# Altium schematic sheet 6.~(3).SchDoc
size 420 x 297 mm
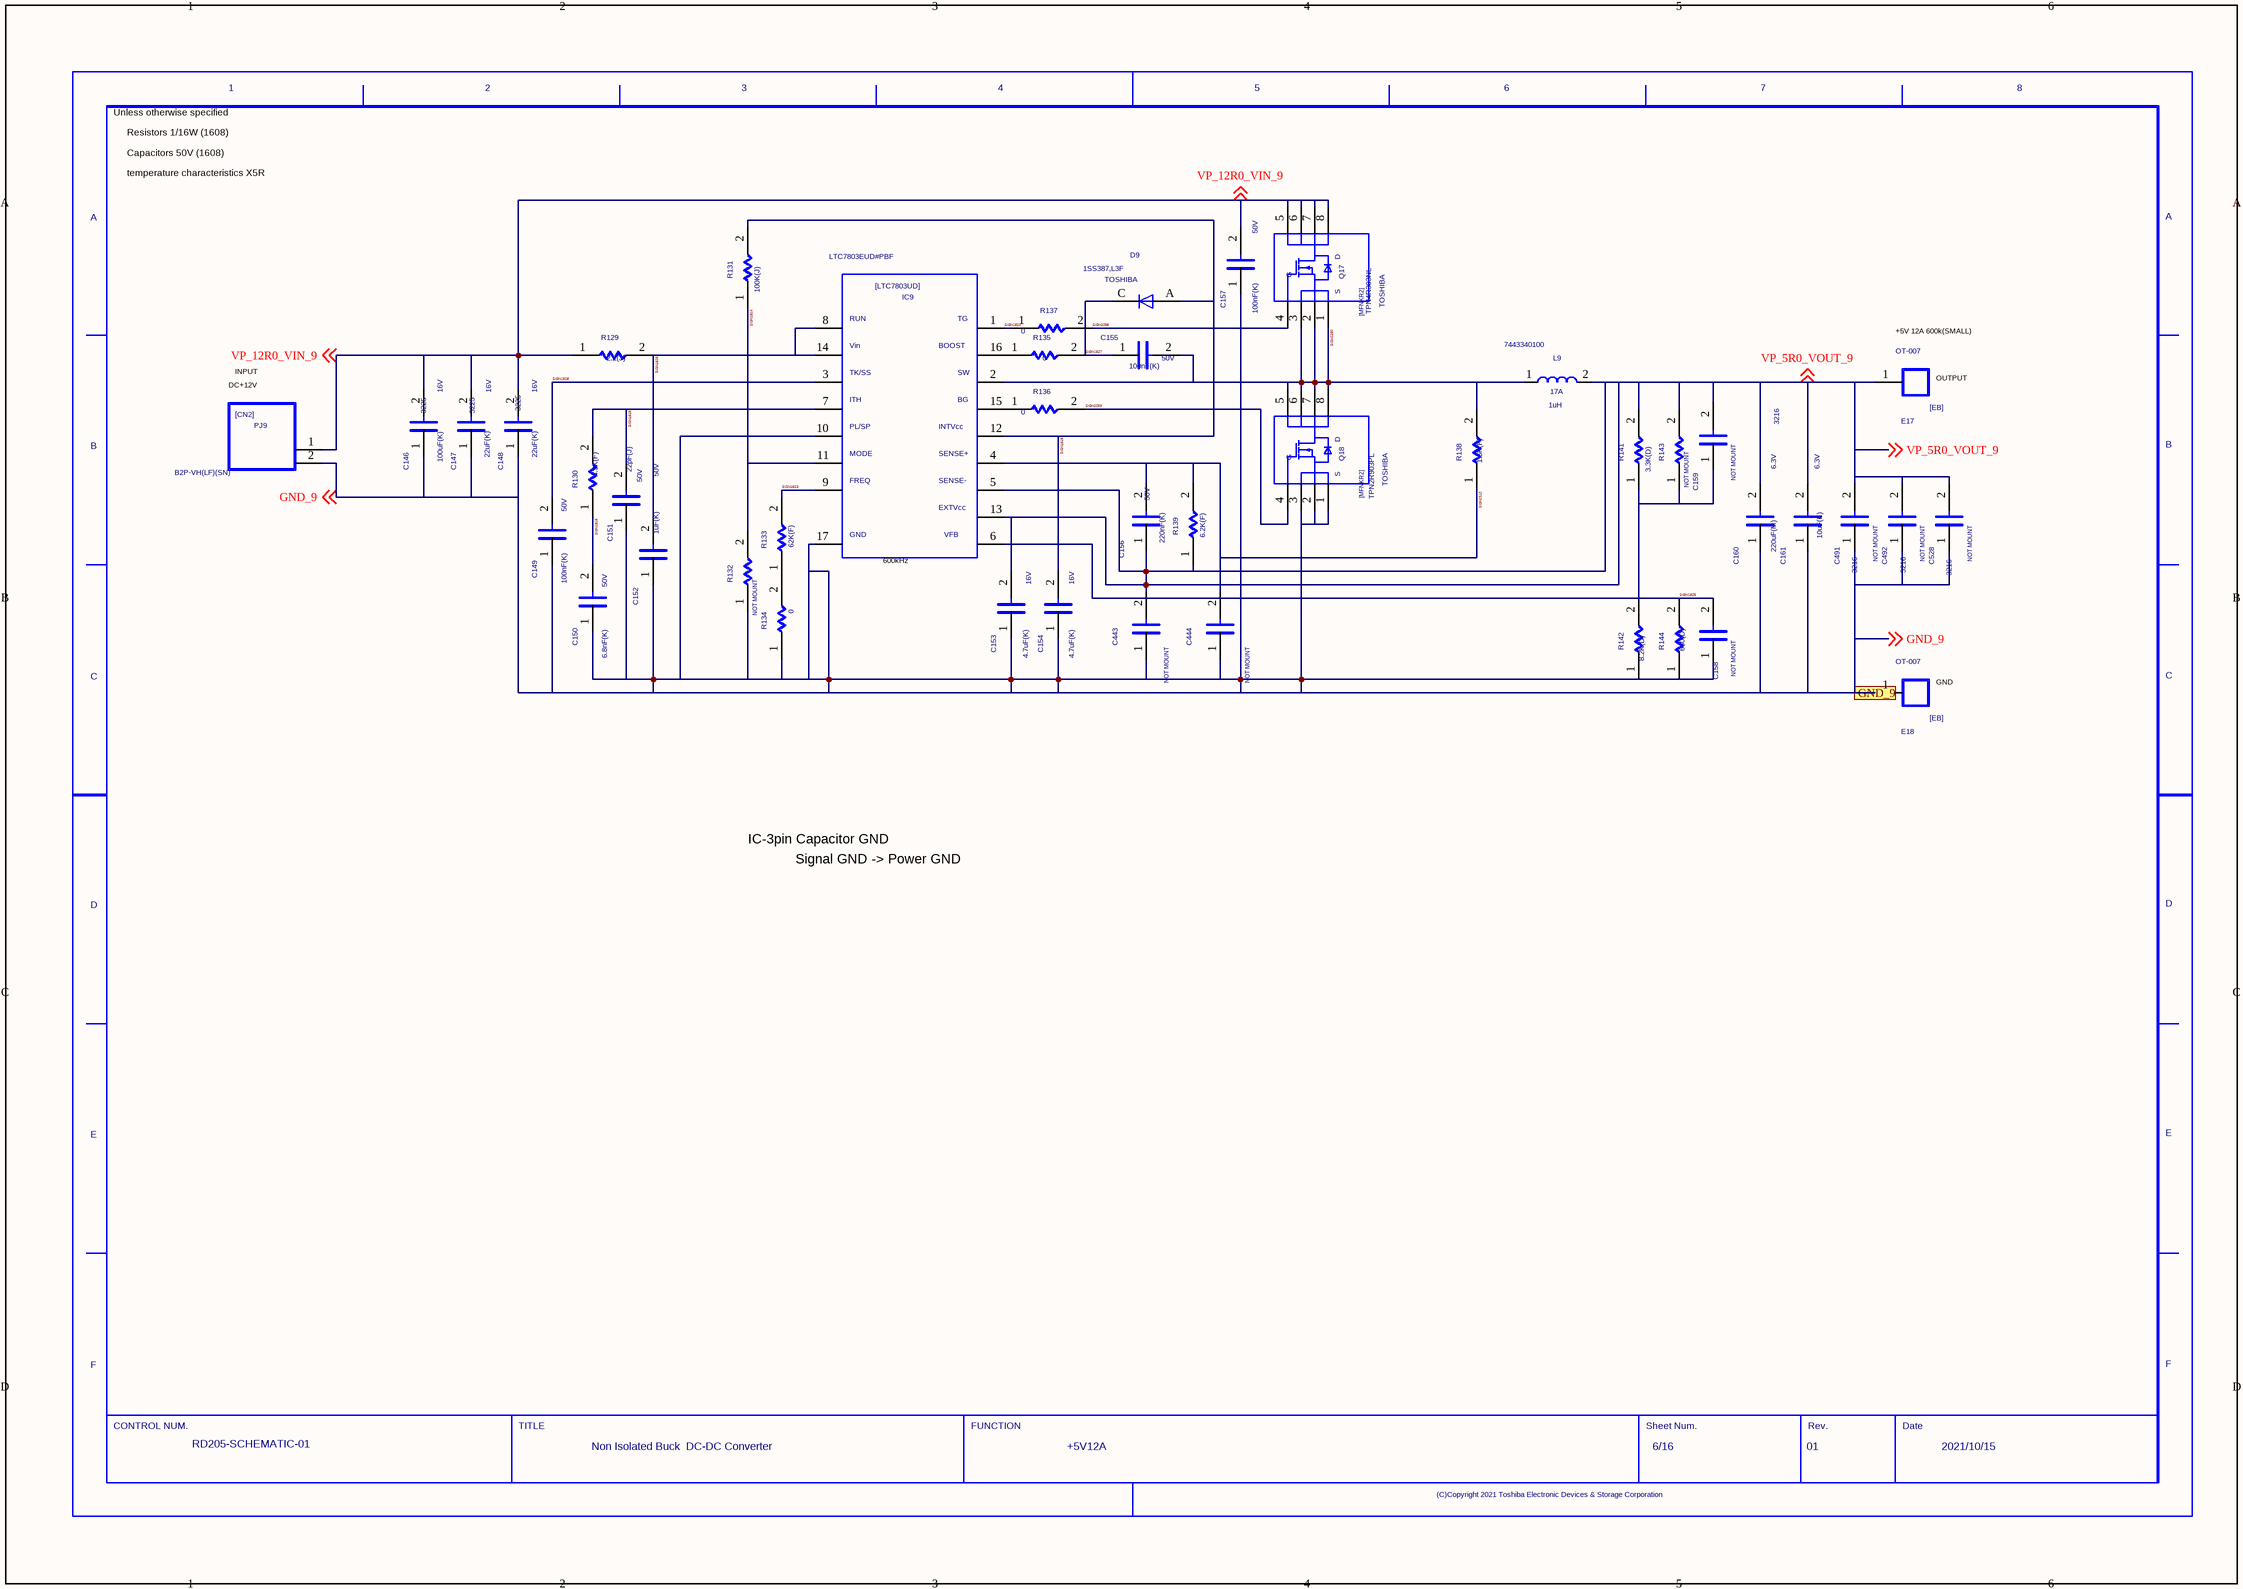
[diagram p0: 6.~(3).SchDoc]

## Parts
C146  SIZECODESMD: 3225  VAL2: 16V  VAL1: 100uF(K)  (hidden comment: C)
C147  SIZECODESMD: 3225  VAL2: 16V  VAL1: 22uF(K)  (hidden comment: C)
C148  SIZECODESMD: 3225  VAL2: 16V  VAL1: 22uF(K)  (hidden comment: C)
C149  VAL2: 50V  VAL1: 100nF(K)  (hidden comment: C)
C150  VAL2: 50V  VAL1: 6.8nF(K)  (hidden comment: C)
C151  VAL2: 50V  VAL1: 22pF(J)  (hidden comment: C)
C152  VAL2: 50V  VAL1: 1uF(K)  (hidden comment: C)
C153  VAL2: 16V  VAL1: 4.7uF(K)  (hidden comment: C)
C154  VAL2: 16V  VAL1: 4.7uF(K)  (hidden comment: C)
C155  VAL2: 50V  VAL1: 100nF(K)  (hidden comment: C)
C156  VAL2: 50V  VAL1: 220nF(K)  (hidden comment: C)
C157  VAL2: 50V  VAL1: 100nF(K)  (hidden comment: C)
C158  NOTMOUNT: NOT MOUNT  (hidden comment: C)
C159  NOTMOUNT: NOT MOUNT  (hidden comment: C)
C160  SIZECODESMD: 3216  VAL2: 6.3V  VAL1: 220uF(M)  (hidden comment: C)
C161  VAL2: 6.3V  VAL1: 10uF(K)  (hidden comment: C)
C443  NOTMOUNT: NOT MOUNT  (hidden comment: C)
C444  NOTMOUNT: NOT MOUNT  (hidden comment: C)
C491  NOTMOUNT: NOT MOUNT  SIZECODESMD: 3216  (hidden comment: C)
C492  NOTMOUNT: NOT MOUNT  SIZECODESMD: 3216  (hidden comment: C)
C528  NOTMOUNT: NOT MOUNT  SIZECODESMD: 3216  (hidden comment: C)
D9  USERCOMPTEXT3: TOSHIBA  VAL3: 1SS387,L3F  (hidden comment: D)
E17  VAL3: OT-007  (hidden comment: EB)
E18  VAL3: OT-007  (hidden comment: EB)
IC9  VAL3: LTC7803EUD#PBF  (hidden comment: LTC7803UD)
L9  VAL3: 7443340100  VAL2: 17A  VAL1: 1uH  (hidden comment: L)
PJ9  VAL3: B2P-VH(LF)(SN)  (hidden comment: CN2)
Q17  USERCOMPTEXT3: TOSHIBA  VAL3: TPN4R303NL  (hidden comment: MFNKR2)
Q18  USERCOMPTEXT3: TOSHIBA  VAL3: TPN2R903PL  (hidden comment: MFNKR2)
R129  VAL1: 2.2(J)  (hidden comment: R)
R130  VAL1: 4.3K(F)  (hidden comment: R)
R131  VAL1: 100K(J)  (hidden comment: R)
R132  NOTMOUNT: NOT MOUNT  (hidden comment: R)
R133  VAL1: 62K(F)  (hidden comment: R)
R134  VAL1: 0  (hidden comment: R)
R135  VAL1: 0  (hidden comment: R)
R136  VAL1: 0  (hidden comment: R)
R137  VAL1: 0  (hidden comment: R)
R138  VAL1: 1.5K(F)  (hidden comment: R)
R139  VAL1: 6.2K(F)  (hidden comment: R)
R141  VAL1: 3.3K(D)  (hidden comment: R)
R142  VAL1: 8.2K(D)  (hidden comment: R)
R143  NOTMOUNT: NOT MOUNT  (hidden comment: R)
R144  VAL1: 680(D)  (hidden comment: R)
U?  DATE: 2021/10/15  SHEETNUMBER: 6/16  TITLE: Non Isolated Buck / DC-DC Converter  REVISION: 01  DRAWINGNUMBER: RD205-SCHEMATIC-01  FUNCTION: +5V12A  (hidden comment: WAKU_DEF100)

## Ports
GND_9

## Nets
GND_9: C146.1 C147.1 C148.1 C149.1 C150.1 C151.1 C152.1 C153.1 C154.1 C157.1 C158.1 C160.1 C161.1 C443.1 C444.1 C491.1 C492.1 C528.1 E18.1 IC9.10 IC9.17 PJ9.2 Q18.1 Q18.2 Q18.3 R132.1 R134.1 R142.1 R144.1 ; off-sheet GND_9, port GND_9
SIGN1814: IC9.11 R131.1 R132.2
SIGN1815: C154.2 D9.A IC9.12 R131.2
SIGN1816: C150.2 R130.1
SIGN1819: C151.2 IC9.7 R130.2
SIGN1822: IC9.1 R137.1
SIGN1823: IC9.9 R133.2
SIGN1825: C158.2 C159.1 IC9.6 R141.1 R142.2 R143.1 R144.2
SIGN1826: C152.2 IC9.8 IC9.14 R129.2
SIGN1827: C155.1 D9.C R135.2
SIGN1828: C149.2 IC9.3
SIGN2258: Q17.4 R137.2
SIGN2259: Q18.4 R136.2
SIGN2260: C155.2 IC9.2 L9.1 Q17.1 Q17.2 Q17.3 Q18.5 Q18.6 Q18.7 Q18.8 R138.2
SIGN2312: C156.2 C444.2 IC9.4 R138.1 R139.2
VP_5R0_VOUT_9: C153.2 C156.1 C159.2 C160.2 C161.2 C443.2 C491.2 C492.2 C528.2 E17.1 IC9.5 IC9.13 L9.2 R139.1 R141.2 R143.2 ; off-sheet VP_5R0_VOUT_9
VP_12R0_VIN_9: C146.2 C147.2 C148.2 C157.2 PJ9.1 Q17.5 Q17.6 Q17.7 Q17.8 R129.1 ; off-sheet VP_12R0_VIN_9
NetIC9_15: IC9.15 R136.1
NetIC9_16: IC9.16 R135.1
NetR133_1: R133.1 R134.2

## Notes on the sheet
- Unless otherwise specified
- Resistors 1/16W (1608)
- Capacitors 50V (1608)
- temperature characteristics X5R
- DC+12V
- INPUT
- (near E17) +5V 12A 600k(SMALL)
- (near E17) OUTPUT
- (near IC9) 600kHz
- (near E18) GND
- IC-3pin Capacitor GND
- Signal GND -> Power GND

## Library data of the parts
C146 = C: SQ_PART_MODEL: CON_100n; FNPARTSNAMEG: CHIP CERAMIC CAPACITOR (3225); USEINPARTSLIST: YES; OriginalSymbolOrigin: (2540,7620); MFSOLDERINGPROP: .; TEMPCHARACTERI2: B; MFFORMINGDIVP: KC; OUMECLASSIFICATION: セラミックコンデンサ; MFMOUNTSYMBOLP: 90; CDMASTERCADCELG: DC903A; PCODE: P03276001115; FNCLASSCODEG: P03-03; MAXGCOUNT: 1; RATEDVOLTAGE: 250; COMPONENTNAME: G36030160049; OUMEMAKER: KYC 京セラ; MFPACKAGEMETHOP: S; NOMINALCAPACITA: 100n; OUMEMAKERKATAMEI: CF32W5R104K250AT; CAPACITANCETOLE: K
C147 C148 = C: SQ_PART_MODEL: CON_22u; FNPARTSNAMEG: CHIP CERAMIC CAPACITOR (3225); USEINPARTSLIST: YES; OriginalSymbolOrigin: (2540,7620); MFSOLDERINGPROP: .; TEMPCHARACTERI2: B; MFFORMINGDIVP: KC; OUMECLASSIFICATION: セラミックコンデンサ; MFMOUNTSYMBOLP: 80; CDMASTERCADCELG: DC903A; PCODE: P03043035626; FNCLASSCODEG: P03-03; MAXGCOUNT: 1; RATEDVOLTAGE: 6.3; COMPONENTNAME: G36030119054; OUMEMAKER: TYD 太陽誘電; MFPACKAGEMETHOP: S; NOMINALCAPACITA: 22u; OUMEMAKERKATAMEI: JMK325BJ226KM-T; CAPACITANCETOLE: K
C149 C155 C157 = C: SQ_PART_MODEL: CON_100n; FNPARTSNAMEG: CHIP CERAMIC CAPACITOR (1608); USEINPARTSLIST: YES; OriginalSymbolOrigin: (2540,7620); MFSOLDERINGPROP: .; TEMPCHARACTERI2: B; MFFORMINGDIVP: KC; OUMECLASSIFICATION: セラミックコンデンサ; SIZECODESMD: 1608; MFMOUNTSYMBOLP: 80; CDMASTERCADCELG: C8100E; PCODE: P03B000000E4; FNCLASSCODEG: P03-03; MAXGCOUNT: 1; RATEDVOLTAGE: 16; COMPONENTNAME: GDM030000598; OUMEMAKER: MRT 村田製作所; MFPACKAGEMETHOP: S; NOMINALCAPACITA: 100n; OUMEMAKERKATAMEI: GRM188B11C104KA01C; CAPACITANCETOLE: K
C150 = C: SQ_PART_MODEL: CON_6.8n; FNPARTSNAMEG: CHIP CERAMIC CAPACITOR (1608); USEINPARTSLIST: YES; OriginalSymbolOrigin: (2540,7620); TOLERANCE: K; ASIMVALUE: 6.8N; MFSOLDERINGPROP: .; TEMPCHARACTERI2: B; MFFORMINGDIVP: KC; OUMECLASSIFICATION: セラミックコンデンサ; SIZECODESMD: 1608; MFMOUNTSYMBOLP: 80; CDMASTERCADCELG: C8100E; PCODE: P03039109225; FNCLASSCODEG: P03-03; MAXGCOUNT: 1; RATEDVOLTAGE: 50; COMPONENTNAME: G36030011440; OUMEMAKER: MRT 村田製作所; MFPACKAGEMETHOP: S; OUMEMAKERKATAMEI: GRM39B682K50PT
C151 = C: SQ_PART_MODEL: CON_22p; FNPARTSNAMEG: CHIP CERAMIC CAPACITOR (1608); USEINPARTSLIST: YES; OriginalSymbolOrigin: (2540,7620); TOLERANCE: J; ASIMVALUE: 22P; MFSOLDERINGPROP: .; TEMPCHARACTERI2: CH; MFFORMINGDIVP: KC; OUMECLASSIFICATION: セラミックコンデンサ; SIZECODESMD: 1608; MFMOUNTSYMBOLP: 80; CDMASTERCADCELG: C8100E; PCODE: P03039A02625; FNCLASSCODEG: P03-03; MAXGCOUNT: 1; RATEDVOLTAGE: 50; COMPONENTNAME: G36030011129; OUMEMAKER: TYD 太陽誘電; MFPACKAGEMETHOP: S; OUMEMAKERKATAMEI: UMK107CH220JZ-T
C152 = C: SQ_PART_MODEL: CON_1u; FNPARTSNAMEG: CHIP CERAMIC CAPACITOR (1608); USEINPARTSLIST: YES; OriginalSymbolOrigin: (2540,7620); MFSOLDERINGPROP: .; TEMPCHARACTERI2: B; MFFORMINGDIVP: KC; OUMECLASSIFICATION: セラミックコンデンサ; SIZECODESMD: 1608; MFMOUNTSYMBOLP: 80; CDMASTERCADCELG: C8100E; PCODE: P03039ACE122; FNCLASSCODEG: P03-03; MAXGCOUNT: 1; RATEDVOLTAGE: 6.3; COMPONENTNAME: G36030104159; OUMEMAKER: KYC 京セラ; MFPACKAGEMETHOP: S; NOMINALCAPACITA: 1u; OUMEMAKERKATAMEI: CM105B105K06ATN; CAPACITANCETOLE: K
C153 = C: SQ_PART_MODEL: CON_4.7u; FNPARTSNAMEG: CHIP CERAMIC CAPACITOR (1608); USEINPARTSLIST: YES; OriginalSymbolOrigin: (2540,7620); PCODE: P03B000000MS; MFSOLDERINGPROP: .; TEMPCHARACTERI2: B; MFFORMINGDIVP: KC; OUMECLASSIFICATION: セラミックコンデンサ; SIZECODESMD: 1608; MFMOUNTSYMBOLP: 80; CDMASTERCADCELG: C8100E; FNCLASSCODEG: P03-03; MAXGCOUNT: 1; RATEDVOLTAGE: 4; COMPONENTNAME: GDM030000053; OUMEMAKER: KYC 京セラ; MFPACKAGEMETHOP: S; NOMINALCAPACITA: 4.7u; OUMEMAKERKATAMEI: CM105B475M04AT; CAPACITANCETOLE: M
C154 = C: SQ_PART_MODEL: CON_4.7u; FNPARTSNAMEG: CHIP CERAMIC CAPACITOR (1608); USEINPARTSLIST: YES; OriginalSymbolOrigin: (2540,7620); MFSOLDERINGPROP: .; TEMPCHARACTERI2: B; MFFORMINGDIVP: KC; OUMECLASSIFICATION: セラミックコンデンサ; SIZECODESMD: 1608; MFMOUNTSYMBOLP: 80; CDMASTERCADCELG: C8100E; PCODE: P03B000000MS; FNCLASSCODEG: P03-03; MAXGCOUNT: 1; RATEDVOLTAGE: 4; COMPONENTNAME: GDM030000053; OUMEMAKER: KYC 京セラ; MFPACKAGEMETHOP: S; NOMINALCAPACITA: 4.7u; OUMEMAKERKATAMEI: CM105B475M04AT; CAPACITANCETOLE: M
C156 = C: SQ_PART_MODEL: CON_220n; FNPARTSNAMEG: CHIP CERAMIC CAPACITOR (1608); PARTCOMMENT: 代表セル<KC0008> がフットプリントに登録されていません。; USEINPARTSLIST: YES; OriginalSymbolOrigin: (2540,7620); MFSOLDERINGPROP: .; TEMPCHARACTERI2: B; MFFORMINGDIVP: KC; OUMECLASSIFICATION: セラミックコンデンサ; SIZECODESMD: 1608; MFMOUNTSYMBOLP: 80; CDMASTERCADCELG: KC0008; PCODE: P03B000001L3; FNCLASSCODEG: P03-03; MAXGCOUNT: 1; RATEDVOLTAGE: 16; COMPONENTNAME: GDM030001129; OUMEMAKER: MRT 村田製作所; MFPACKAGEMETHOP: S; NOMINALCAPACITA: 220n; OUMEMAKERKATAMEI: GRM188B11C224KA01D; CAPACITANCETOLE: K
C158 C159 = C: SQ_PART_MODEL: CON_100p; FNPARTSNAMEG: CHIP CERAMIC CAPACITOR (1608); USEINPARTSLIST: YES; OriginalSymbolOrigin: (2540,7620); TOLERANCE: J; ASIMVALUE: 100P; MFSOLDERINGPROP: .; TEMPCHARACTERI2: CH; MFFORMINGDIVP: KC; OUMECLASSIFICATION: セラミックコンデンサ; SIZECODESMD: 1608; MFMOUNTSYMBOLP: 80; CDMASTERCADCELG: C8100E; PCODE: P03039177125; FNCLASSCODEG: P03-03; MAXGCOUNT: 1; RATEDVOLTAGE: 50; COMPONENTNAME: G36030011365; OUMEMAKER: KYC 京セラ; MFPACKAGEMETHOP: S; OUMEMAKERKATAMEI: CM105CH101J50AT; VAL2: 50V; VAL1: 100pF(J)
C160 = C: SQ_PART_MODEL: CON_22u; FNPARTSNAMEG: CHIP CERAMIC CAPACITOR (3216); USEINPARTSLIST: YES; OriginalSymbolOrigin: (2540,7620); MFSOLDERINGPROP: .; TEMPCHARACTERI2: B; MFFORMINGDIVP: KC; OUMECLASSIFICATION: セラミックコンデンサ; MFMOUNTSYMBOLP: 80; CDMASTERCADCELG: DC901A; PCODE: P03B0000004V; FNCLASSCODEG: P03-03; MAXGCOUNT: 1; RATEDVOLTAGE: 6.3; COMPONENTNAME: GDM030000020; OUMEMAKER: KYC 京セラ; MFPACKAGEMETHOP: S; NOMINALCAPACITA: 22u; OUMEMAKERKATAMEI: CM316B226M06AT; CAPACITANCETOLE: M
C161 = C: SQ_PART_MODEL: CON_1u; FNPARTSNAMEG: CHIP CERAMIC CAPACITOR (1608); PARTCOMMENT: 代表セル<KC0008> がフットプリントに登録されていません。; USEINPARTSLIST: YES; OriginalSymbolOrigin: (2540,7620); MFSOLDERINGPROP: .; TEMPCHARACTERI2: B; MFPACKAGEMETHOP: S; MFFORMINGDIVP: KC; MFMOUNTSYMBOLP: 80; PCODE: P03B000000ZQ; OUMECLASSIFICATION: セラミックコンデンサ; SIZECODESMD: 1608; CDMASTERCADCELG: KC0008; FNCLASSCODEG: P03-03; MAXGCOUNT: 1; RATEDVOLTAGE: 6.3; COMPONENTNAME: GDM030000202; OUMEMAKER: MRT 村田製作所; NOMINALCAPACITA: 1u; OUMEMAKERKATAMEI: GRM185B10J105KE21D; CAPACITANCETOLE: K
C443 C444 = C: SQ_PART_MODEL: CON_220n; FNPARTSNAMEG: CHIP CERAMIC CAPACITOR (1608); PARTCOMMENT: 代表セル<KC0008> がフットプリントに登録されていません。; USEINPARTSLIST: YES; OriginalSymbolOrigin: (2540,7620); MFSOLDERINGPROP: .; TEMPCHARACTERI2: B; MFFORMINGDIVP: KC; OUMECLASSIFICATION: セラミックコンデンサ; SIZECODESMD: 1608; MFMOUNTSYMBOLP: 80; CDMASTERCADCELG: KC0008; PCODE: P03B000001L3; FNCLASSCODEG: P03-03; MAXGCOUNT: 1; RATEDVOLTAGE: 16; COMPONENTNAME: GDM030001129; OUMEMAKER: MRT 村田製作所; MFPACKAGEMETHOP: S; NOMINALCAPACITA: 220n; OUMEMAKERKATAMEI: GRM188B11C224KA01D; VAL2: 16V; VAL1: 220nF(K); CAPACITANCETOLE: K
C491 C492 C528 = C: SQ_PART_MODEL: CON_22u; FNPARTSNAMEG: CHIP CERAMIC CAPACITOR (3216); USEINPARTSLIST: YES; OriginalSymbolOrigin: (2540,7620); MFSOLDERINGPROP: .; TEMPCHARACTERI2: B; MFFORMINGDIVP: KC; OUMECLASSIFICATION: セラミックコンデンサ; MFMOUNTSYMBOLP: 80; CDMASTERCADCELG: DC901A; PCODE: P03B0000004V; FNCLASSCODEG: P03-03; MAXGCOUNT: 1; RATEDVOLTAGE: 6.3; COMPONENTNAME: GDM030000020; OUMEMAKER: KYC 京セラ; MFPACKAGEMETHOP: S; NOMINALCAPACITA: 22u; OUMEMAKERKATAMEI: CM316B226M06AT; VAL2: 6.3V; VAL1: 22uF(M); CAPACITANCETOLE: M
D9 = D: FNPARTSNAMEG: DIODE; USEINPARTSLIST: YES; PARTNAME: GDM420000143; SAVEAREA0: -565,-171,12979,8058; SAVECOUNT: 1; TIME: 14:49:55; UPDATEUSER: 19870035; UPDATETIME: 14:20:16; OriginalSymbolOrigin: (5080,5080); FORWARDVOLTAGEM: 0; MAXREVERSEVOLTA: 80; COMPONENTNAME: GDM420000143_package; MFSOLDERINGPROP: .; OUMEMAKER: TSB 東芝（ＹＰＳＳ）; QUADMODEL: dummymodel; MFPACKAGEMETHOP: S; MFFORMINGDIVP: MM; MOUNTINGFORMSMD: SMD; OUMECLASSIFICATION: 小信号ダイオード; OUMEMAKERKATAMEI: 1SS387(TPH3,F); CDMASTERCADCELG: D8101D; PCODE: P42B0000008E; FNCLASSCODEG: P42-01
E17 E18 = EB: FNPARTSNAMEG: TERMINAL; USEINPARTSLIST: YES; PARTNAME: 5P9L1232P001; OUMEPARTTYPE: TB; OriginalSymbolOrigin: (2540,12700); COMPONENTNAME: 5P9L1232P001_package; MAXGCOUNT: 1; MFSOLDERINGPROP: .; OUMEMAKER: オサダ; QUADMODEL: dummymodel; MFPACKAGEMETHOP: I; MFFORMINGDIVP: OD; OUMECLASSIFICATION: 端子台、端子板; CDMASTERCADCELG: DE0009; KIND: PBS; PCODE: P29045001117; TERMINALSTYLE: SC; FNCLASSCODEG: P29-01
IC9 = LTC7803UD: USEINPARTSLIST: YES; SAVECOUNT: 29; SAVEAREA0: -53177,0,89020,58420; TIME: 16:14:14; UPDATEUSER: q91866sr; UPDATETIME: 13:15:36; OriginalSymbolOrigin: (5080,55880); MAXGCOUNT: 1; COMPONENTNAME: LTC7803UD_LTC7803UD; OUMEMAKER: ANALOG DEVICES
L9 = L: USEINPARTSLIST: YES; PARTNAME: 7443340068; OriginalSymbolOrigin: (2540,5080); MAXGCOUNT: 1; COMPONENTNAME: L_L; OUMEMAKER: WURTH
PJ9 = CN2: FNPARTSNAMEG: 3.96PITCH NYLON CONNECTOR; USEINPARTSLIST: YES; PARTNAME: G36220114012; OUMEPARTTYPE: CN; OriginalSymbolOrigin: (2540,15240); MAXGCOUNT: 1; RATEDCURRENT: 7; COMPONENTNAME: G36220114012_package; MFSOLDERINGPROP: .; OUMEMAKER: JST 日本圧着端子製造; NUMBEROFCONTACT: 2; QUADMODEL: dummymodel; MFPACKAGEMETHOP: I; MFFORMINGDIVP: CU; CONTACTPITCH: 3.96m; OUMEMAKERKATAMEI: B2P-VH; CDMASTERCADCELG: DPJ514; PCODE: P22346001114; TERMINALSTYLE: PW; FNCLASSCODEG: P22-10
Q17 Q18 = MFNKR2: USEINPARTSLIST: YES; PARTNAME: TPN1R603PL; SAVEAREA0: -9199,-39,32138,22820; TIME: 18:57:44; UPDATEUSER: q91866sr; UPDATETIME: 12:36:02; SAVECOUNT: 10; OriginalSymbolOrigin: (5080,20320); MAXGCOUNT: 1; COMPONENTNAME: MFNKR2_MFNKR2
R129 = R: SQ_PART_MODEL: RES_2.2; FNPARTSNAMEG: CHIP RESISTOR (1608); USEINPARTSLIST: YES; OriginalSymbolOrigin: (5080,5080); TOLERANCE: J; ASIMVALUE: 2.2; MAXGCOUNT: 1; COMPONENTNAME: G36010011507; MFSOLDERINGPROP: .; OUMEMAKER: NAE 松下電子部品; MFPACKAGEMETHOP: S; MFFORMINGDIVP: KC; MOUNTINGFORMSMD: SMD; OUMECLASSIFICATION: 表面実装用固定抵抗器; MFMOUNTSYMBOLP: 80; POWERRATING: 63m; OUMEMAKERKATAMEI: ERJ3GEYJ2R2V; NUMBEROFELEMENT: 0; VAL2: 62.5mW; CDMASTERCADCELG: DR802R; PCODE: P01042157622; FNCLASSCODEG: P01-08
R130 = R: SQ_PART_MODEL: RES_4.3K; FNPARTSNAMEG: CHIP RESISTOR (1608); USEINPARTSLIST: YES; OriginalSymbolOrigin: (5080,5080); PCODE: P01042335624; MAXGCOUNT: 1; COMPONENTNAME: G5101105L102; MFSOLDERINGPROP: .; OUMEMAKER: NAE 松下電子部品; MFPACKAGEMETHOP: S; MFFORMINGDIVP: KC; MOUNTINGFORMSMD: SMD; OUMECLASSIFICATION: 表面実装用固定抵抗器; RESISTANCETOLER: F; MFMOUNTSYMBOLP: 80; POWERRATING: 63m; OUMEMAKERKATAMEI: ERJ3GEYF432V; NOMINALRESISTAN: 4.3K; NUMBEROFELEMENT: 0; VAL2: 62.5mW; CDMASTERCADCELG: DR802R; FNCLASSCODEG: P01-08
R131 = R: SQ_PART_MODEL: RES_100K; FNPARTSNAMEG: CHIP RESISTOR (1608); USEINPARTSLIST: YES; OriginalSymbolOrigin: (5080,5080); TOLERANCE: J; ASIMVALUE: 100K; MFSOLDERINGPROP: .; MFPACKAGEMETHOP: S; MFFORMINGDIVP: KC; MOUNTINGFORMSMD: SMD; MFMOUNTSYMBOLP: 80; NUMBEROFELEMENT: 0; PCODE: P01042047220; MAXGCOUNT: 1; COMPONENTNAME: G36010011057; OUMEMAKER: HDK 北陸電気工業; OUMECLASSIFICATION: 表面実装用固定抵抗器; POWERRATING: 63m; OUMEMAKERKATAMEI: CR1/16 104JV; VAL2: 62.5mW; CDMASTERCADCELG: DR802R; FNCLASSCODEG: P01-08
R132 = R: SQ_PART_MODEL: RES_10; FNPARTSNAMEG: CHIP RESISTOR (1608); USEINPARTSLIST: YES; OriginalSymbolOrigin: (5080,5080); TOLERANCE: F; ASIMVALUE: 10; MFSOLDERINGPROP: .; MFPACKAGEMETHOP: S; MFFORMINGDIVP: KC; MOUNTINGFORMSMD: SMD; MFMOUNTSYMBOLP: 80; NUMBEROFELEMENT: 0; PCODE: P01042036620; MAXGCOUNT: 1; COMPONENTNAME: G36010104063; OUMEMAKER: NAE 松下電子部品; OUMECLASSIFICATION: 表面実装用固定抵抗器; POWERRATING: 63m; OUMEMAKERKATAMEI: ERJ3GEYF100V; VAL2: 62.5mW; VAL1: 10(F); CDMASTERCADCELG: DR802R; FNCLASSCODEG: P01-08
R133 = R: SQ_PART_MODEL: RES_62K; FNPARTSNAMEG: CHIP RESISTOR (1608); USEINPARTSLIST: YES; OriginalSymbolOrigin: (5080,5080); MAXGCOUNT: 1; TOLERANCE: F; COMPONENTNAME: G36010027355; MFSOLDERINGPROP: .; OUMEMAKER: HDK 北陸電気工業; MFPACKAGEMETHOP: S; MFFORMINGDIVP: KC; MOUNTINGFORMSMD: SMD; OUMECLASSIFICATION: 表面実装用固定抵抗器; ASIMVALUE: 62K; MFMOUNTSYMBOLP: 80; POWERRATING: 63m; OUMEMAKERKATAMEI: CR1/16 623FV; NUMBEROFELEMENT: 0; VAL2: 62.5mW; CDMASTERCADCELG: DR802R; PCODE: P01042441226; FNCLASSCODEG: P01-08
R134 = R: SQ_PART_MODEL: RES_10; FNPARTSNAMEG: CHIP RESISTOR (1608); USEINPARTSLIST: YES; OriginalSymbolOrigin: (5080,5080); TOLERANCE: F; ASIMVALUE: 10; MAXGCOUNT: 1; COMPONENTNAME: G36010104063; MFSOLDERINGPROP: .; OUMEMAKER: NAE 松下電子部品; MFPACKAGEMETHOP: S; MFFORMINGDIVP: KC; MOUNTINGFORMSMD: SMD; OUMECLASSIFICATION: 表面実装用固定抵抗器; MFMOUNTSYMBOLP: 80; POWERRATING: 63m; OUMEMAKERKATAMEI: ERJ3GEYF100V; VAL2: 62.5mW; CDMASTERCADCELG: DR802R; PCODE: P01042036620; FNCLASSCODEG: P01-08
R135 = R: SQ_PART_MODEL: RES_10; FNPARTSNAMEG: CHIP RESISTOR (1608); USEINPARTSLIST: YES; OriginalSymbolOrigin: (5080,5080); TOLERANCE: F; ASIMVALUE: 10; MFSOLDERINGPROP: .; MFPACKAGEMETHOP: S; MFFORMINGDIVP: KC; MOUNTINGFORMSMD: SMD; MFMOUNTSYMBOLP: 80; PCODE: P01042036620; MAXGCOUNT: 1; COMPONENTNAME: G36010104063; OUMEMAKER: NAE 松下電子部品; OUMECLASSIFICATION: 表面実装用固定抵抗器; POWERRATING: 63m; OUMEMAKERKATAMEI: ERJ3GEYF100V; VAL2: 62.5mW; CDMASTERCADCELG: DR802R; FNCLASSCODEG: P01-08
R136 R137 = R: SQ_PART_MODEL: RES_10; FNPARTSNAMEG: CHIP RESISTOR (2012); USEINPARTSLIST: YES; OriginalSymbolOrigin: (5080,5080); MAXGCOUNT: 1; TOLERANCE: F; COMPONENTNAME: 5P9L1083P100; MFSOLDERINGPROP: .; OUMEMAKER: 北陸電気工業; MFPACKAGEMETHOP: S; MFFORMINGDIVP: KC; MOUNTINGFORMSMD: SMD; OUMECLASSIFICATION: 表面実装用固定抵抗器; ASIMVALUE: 10; MFMOUNTSYMBOLP: 90; POWERRATING: 100m; OUMEMAKERKATAMEI: CR1/10 100FV Pb(F); VAL2: 125mW; CDMASTERCADCELG: DR910A; PCODE: P01043091222; FNCLASSCODEG: P01-08
R138 = R: SQ_PART_MODEL: RES_1.5K; FNPARTSNAMEG: CHIP RESISTOR (1608); USEINPARTSLIST: YES; OriginalSymbolOrigin: (5080,5080); TOLERANCE: F; ASIMVALUE: 1.5K; MAXGCOUNT: 1; COMPONENTNAME: G36010027232; MFSOLDERINGPROP: .; OUMEMAKER: HDK 北陸電気工業; MFPACKAGEMETHOP: S; MFFORMINGDIVP: KC; MOUNTINGFORMSMD: SMD; OUMECLASSIFICATION: 表面実装用固定抵抗器; MFMOUNTSYMBOLP: 80; POWERRATING: 63m; OUMEMAKERKATAMEI: CR1/16 152FV; NUMBEROFELEMENT: 0; VAL2: 62.5mW; CDMASTERCADCELG: DR802R; PCODE: P01042512223; FNCLASSCODEG: P01-08
R139 = R: SQ_PART_MODEL: RES_6.2K; FNPARTSNAMEG: CHIP RESISTOR (1608); USEINPARTSLIST: YES; OriginalSymbolOrigin: (5080,5080); TOLERANCE: F; ASIMVALUE: 6.2K; MAXGCOUNT: 1; COMPONENTNAME: G36010027119; MFSOLDERINGPROP: .; OUMEMAKER: KOA ＫＯＡ; MFPACKAGEMETHOP: S; MFFORMINGDIVP: KC; MOUNTINGFORMSMD: SMD; OUMECLASSIFICATION: 表面実装用固定抵抗器; MFMOUNTSYMBOLP: 80; POWERRATING: 63m; OUMEMAKERKATAMEI: RK73H1JTD6201F; NUMBEROFELEMENT: 0; VAL2: 62.5mW; CDMASTERCADCELG: DR802R; PCODE: P01042419423; FNCLASSCODEG: P01-08
R141 = R: SQ_PART_MODEL: RES_3.3K; FNPARTSNAMEG: CHIP RESISTOR (1608); USEINPARTSLIST: YES; OriginalSymbolOrigin: (5080,5080); MAXGCOUNT: 1; COMPONENTNAME: G36010014485; MFSOLDERINGPROP: .; OUMEMAKER: SSM 進工業; MFPACKAGEMETHOP: S; MFFORMINGDIVP: KC; MOUNTINGFORMSMD: SMD; OUMECLASSIFICATION: 表面実装用固定抵抗器; RESISTANCETOLER: D; MFMOUNTSYMBOLP: 80; POWERRATING: 63m; OUMEMAKERKATAMEI: RR0816P-332-D; NOMINALRESISTAN: 3.3K; NUMBEROFELEMENT: 0; VAL2: 62.5mW; CDMASTERCADCELG: DR802R; PCODE: P01042249822; FNCLASSCODEG: P01-08
R142 = R: ICX_PART_MODEL: RES_8.2K; FNPARTSNAMEG: CHIP RESISTOR (1608); OriginalSymbolOrigin: (5080,5080); FNCLASSCODEG: P01-08; PCODE: P01117051114; CDMASTERCADCELG: DR802R; USEWITHSCHEMA: YES; VAL2: 62.5mW; NUMBEROFELEMENT: 0; NOMINALRESISTAN: 8.2K; OUMEMAKERKATAMEI: RK73G1JTD822D; POWERRATING: 63m; MFMOUNTSYMBOLP: 80; RESISTANCETOLER: D; FUNCTION: G36010129479; OUMECLASSIFICATION: 表面実装用固定抵抗器; MOUNTINGFORMSMD: SMD; MFFORMINGDIVP: KC; MFPACKAGEMETHOP: S; OUMEMAKER: KOA ＫＯＡ; MFSOLDERINGPROP: .; MAXGCOUNT: 1
R143 = R: SQ_PART_MODEL: RES_3.3K; FNPARTSNAMEG: CHIP RESISTOR (1608); USEINPARTSLIST: YES; OriginalSymbolOrigin: (5080,5080); TOLERANCE: F; ASIMVALUE: 3.3K; MAXGCOUNT: 1; COMPONENTNAME: G36010027027; MFSOLDERINGPROP: .; OUMEMAKER: ROH ロー・; MFPACKAGEMETHOP: S; MFFORMINGDIVP: KC; MOUNTINGFORMSMD: SMD; OUMECLASSIFICATION: 表面実装用固定抵抗器; MFMOUNTSYMBOLP: 80; POWERRATING: 63m; OUMEMAKERKATAMEI: MCR03EZPFX3301; NUMBEROFELEMENT: 0; VAL2: 62.5mW; VAL1: 3.3K(F); CDMASTERCADCELG: DR802R; PCODE: P01042250729; FNCLASSCODEG: P01-08
R144 = R: ICX_PART_MODEL: RES_680; FNPARTSNAMEG: CHIP RESISTOR (1608); OriginalSymbolOrigin: (5080,5080); FNCLASSCODEG: P01-08; PCODE: P01117025115; CDMASTERCADCELG: DR802R; USEWITHSCHEMA: YES; VAL2: 62.5mW; NUMBEROFELEMENT: 0; NOMINALRESISTAN: 680; OUMEMAKERKATAMEI: RK73G1JTD681D; POWERRATING: 63m; MFMOUNTSYMBOLP: 80; RESISTANCETOLER: D; FUNCTION: G36010129219; OUMECLASSIFICATION: 表面実装用固定抵抗器; MOUNTINGFORMSMD: SMD; MFFORMINGDIVP: KC; MFPACKAGEMETHOP: S; OUMEMAKER: KOA ＫＯＡ; MFSOLDERINGPROP: .; MAXGCOUNT: 1
U? = WAKU_DEF100: PLOTTIME: HH:MM; SAVEAREA0: 330961,54,387907,31546; TIME: 19:23:07; UPDATEUSER: t5459927; UPDATETIME: 15:33:40; SAVECOUNT: 6; OriginalSymbolOrigin: (10160,284480); DESIGNED: ***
